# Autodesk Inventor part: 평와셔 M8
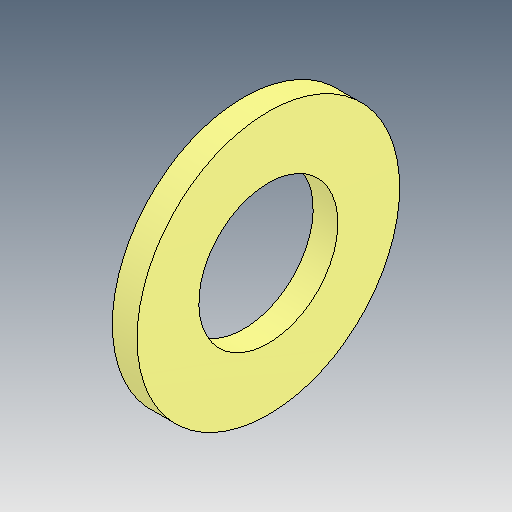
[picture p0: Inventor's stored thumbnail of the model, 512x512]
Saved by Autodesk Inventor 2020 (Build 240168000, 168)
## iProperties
Created: 2024-11
Part Number: 평와셔 M8
Material: 강철, 연강
Description: 평면 와셔
Document SubType Name: Modeling
Designer: shin
Density: 7.85 g/cm^3
Appearance: 기본값
Author: jhkim
Sending System: Autodesk Inventor 2025
Preprocessor: ST-DEVELOPER v20
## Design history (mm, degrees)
feature "Solid1"
node "솔리드1"
